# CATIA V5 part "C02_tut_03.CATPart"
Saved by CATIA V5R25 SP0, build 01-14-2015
Part number: Part1
Bounding box of the stored display mesh (mm): x 0 to 0, y -40 to 40, z -30 to 30
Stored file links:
  E:\ashutosh\Academics\Catia\CATIA V5-6R2013_partfiles\Tutorials_ver_2\C02_tut_03.CATPart
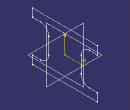
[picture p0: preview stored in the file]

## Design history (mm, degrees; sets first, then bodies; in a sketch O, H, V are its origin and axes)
Body1 (main body)
  Sketch1 on yz-plane, origin (0, 0, 0), H (0, 1, 0), V (0, 0, 1)
    line L1 (-40, -30) -> (40, -30)
    line L2 (40, -30) -> (40, -20)
    line L3 (40, -20) -> (30, -20)
    arc A1 centre (30, -10) radius 10 from (30, -20) to (20, -10) cw
    line L4 (20, -10) -> (20, 10)
    arc A2 centre (30, 10) radius 10 from (20, 10) to (30, 20) cw
    line L5 (30, 20) -> (40, 20)
    point P10 (40, 20)
    line L6 (40, 20) -> (40, 30)
    line L7 (40, 30) -> (-40, 30)
    line L8 (-40, 30) -> (-40, 20)
    point P13 (-40, 20)
    line L9 (-40, 20) -> (-30, 20)
    arc A3 centre (-30, 10) radius 10 from (-30, 20) to (-20, 10) cw
    line L10 (-20, 10) -> (-20, -10)
    arc A4 centre (-30, -10) radius 10 from (-20, -10) to (-30, -20) cw
    point P19 (-30, -20)
    line L11 (-30, -20) -> (-40, -20)
    point P20 (-40, -20)
    line L12 (-40, -20) -> (-40, -30)
    horizontal: L1 H, L3 H, L7 H
    vertical: L2 V, L6 V, L8 V
    tangency: A1 L2, A1 L3, L4 A1, A2 L2, A2 L4, L5 A2, L9 A2, A3 L8, A3 L9, L10 A3, A4 A3, A4 L10, L11 A4, L12 A3
    coincidence: P10 L2, P13 L5, P19 L3, P20 L8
